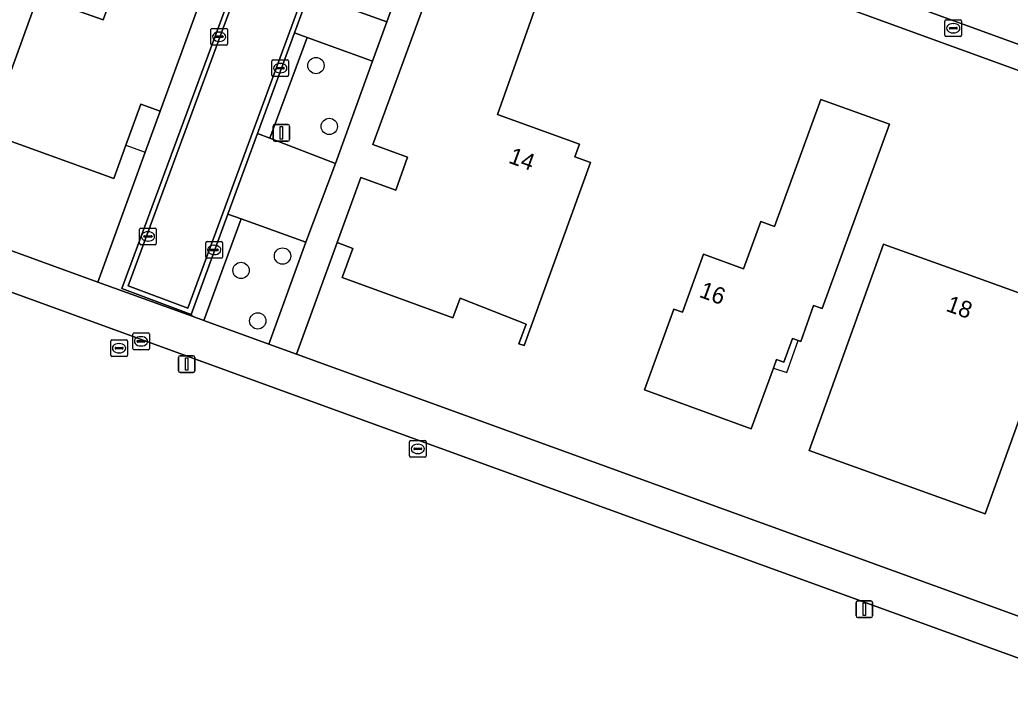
# Model space of a CAD drawing. Extents: x 155275 to 156265, y 382654 to 383635.
# Drawn here: x 155751 to 155810.4, y 382889.5 to 382930.7 of the extents above; entities that cross this region are included whole.
import ezdxf

# ---------------------------------------------------------------- set-up
doc = ezdxf.new("R2010")
doc.units = 0
for name, color, linetype in [('IMGEO_Boom', 7, 'Continuous'), ('IMGEO_Brandkraan', 7, 'Continuous'), ('IMGEO_Erf', 7, 'Continuous'), ('IMGEO_Groenvoorziening', 7, 'Continuous'), ('IMGEO_Kolk', 7, 'Continuous'), ('IMGEO_Lichtmast', 7, 'Continuous'), ('IMGEO_Loofbos', 7, 'Continuous'), ('IMGEO_Pand', 7, 'Continuous'), ('IMGEO_Pand_nummerreeks', 7, 'Continuous'), ('IMGEO_Pand_overbouw', 7, 'Continuous'), ('IMGEO_Parkeervlak_open', 7, 'Continuous'), ('IMGEO_Rijbaan_lokaal_gesloten', 7, 'Continuous'), ('IMGEO_Rijbaan_lokaal_open', 7, 'Continuous'), ('IMGEO_Rioolput', 7, 'Continuous'), ('IMGEO_Voetpad_open', 7, 'Continuous')]:
    doc.layers.add(name, color=color, linetype=linetype)

msp = doc.modelspace()

# ---------------------------------------------------------------- linework, layer by layer
at = {"layer": 'IMGEO_Boom'}
for centre in [(155768.76, 382927.949), (155769.558, 382924.296), (155766.753, 382916.521), (155764.265, 382915.657), (155765.27, 382912.636)]:
    msp.add_circle(centre, 0.489, dxfattribs=at)
at = {"layer": 'IMGEO_Brandkraan'}
for p, q in [((155806.471, 382929.76), (155806.471, 382930.612)), ((155806.546, 382930.686), (155807.398, 382930.686)), ((155806.773, 382930.229), (155807.171, 382930.229)), ((155806.959, 382930.466), (155806.984, 382930.466)), ((155807.472, 382930.612), (155807.472, 382929.76)), ((155807.398, 382929.686), (155806.546, 382929.686)), ((155806.73, 382930.18), (155806.73, 382930.192)), ((155807.168, 382930.143), (155806.77, 382930.143)), ((155806.982, 382929.906), (155806.957, 382929.906)), ((155807.214, 382930.192), (155807.214, 382930.18))]:
    msp.add_line(p, q, dxfattribs=at)
for points in [[(155806.471, 382929.76), (155806.471, 382930.612)], [(155806.546, 382930.686), (155807.398, 382930.686)], [(155807.472, 382930.612), (155807.472, 382929.76)], [(155807.398, 382929.686), (155806.546, 382929.686)]]:
    msp.add_lwpolyline(points, dxfattribs=at)
for centre, radius, start, end in [((155806.548, 382930.61), 0.0765, 91.55205, 178.44795), ((155806.548, 382930.61), 0.0765, 91.55205, 178.44795), ((155806.77, 382930.189), 0.0403, 85.87752, 175.75265), ((155807.175, 382930.191), 0.0386, 1.73085, 96.63898), ((155807.396, 382930.61), 0.0765, 1.55205, 88.44795), ((155807.396, 382930.61), 0.0765, 1.55205, 88.44795), ((155806.548, 382929.762), 0.0765, 181.55205, 268.44795), ((155806.548, 382929.762), 0.0765, 181.55205, 268.44795), ((155806.767, 382930.179), 0.0366, 178.93798, 274.71019), ((155807.171, 382930.186), 0.043, 264.86636, 352.45326), ((155807.396, 382929.762), 0.0765, 271.55205, 358.44795), ((155807.396, 382929.762), 0.0765, 271.55205, 358.44795)]:
    msp.add_arc(centre, radius, start, end, dxfattribs=at)
for centre, major_axis, ratio, start_param, end_param in [((155806.958, 382930.186), (-0.387, 0.002), 0.722429, 4.712389, 7.853982), ((155806.983, 382930.186), (-0.39, 0.002), 0.717154, 1.570796, 4.712389)]:
    msp.add_ellipse(centre, major_axis=major_axis, ratio=ratio, start_param=start_param, end_param=end_param, dxfattribs=at)
at = {"layer": 'IMGEO_Erf'}
msp.add_lwpolyline([(155687.76, 382939.71), (155755.688, 382914.965), (155758.527, 382922.75), (155759.423, 382925.217), (155758.257, 382925.64), (155757.362, 382923.173), (155756.634, 382921.166), (155749.104, 382923.897), (155752.078, 382932.095), (155756.001, 382930.696), (155756.874, 382933.113), (155758.826, 382938.522), (155755.741, 382939.635), (155758.254, 382946.596), (155763.431, 382944.727), (155762.488, 382941.996), (155765.175, 382941.027), (155765.55, 382942.058)], dxfattribs=at)
for points in [[(155858.578, 382910.318), (155778.11, 382939.582), (155776.003, 382933.692), (155781.968, 382931.558), (155779.643, 382925.014), (155784.554, 382923.227), (155784.283, 382922.477), (155785.216, 382922.133), (155781.233, 382911.153), (155780.932, 382911.263), (155781.358, 382912.438), (155777.396, 382913.993), (155776.968, 382912.818), (155770.335, 382915.238), (155770.972, 382916.985), (155770.033, 382917.328), (155767.593, 382910.639), (155854.498, 382879.089), (155856.191, 382884.092), (155849.881, 382886.353), (155855.747, 382902.481), (155860.835, 382896.859), (155862.363, 382901.052), (155857.263, 382906.66)], [(155799.119, 382913.373), (155798.593, 382913.564), (155797.827, 382911.392), (155797.667, 382911.454), (155797.338, 382911.582), (155796.815, 382910.155), (155796.373, 382910.316), (155796.184, 382909.801), (155794.846, 382906.153), (155788.459, 382908.493), (155790.224, 382913.329), (155790.743, 382913.151), (155792.004, 382916.632), (155794.386, 382915.756), (155795.428, 382918.588), (155796.245, 382918.296), (155799.029, 382925.92), (155803.141, 382924.424)], [(155808.882, 382901.058), (155798.327, 382904.865), (155802.783, 382917.235), (155803.058, 382917.132), (155807.739, 382915.451), (155813.345, 382913.432)]]:
    msp.add_lwpolyline(points, close=True, dxfattribs=at)
at = {"layer": 'IMGEO_Groenvoorziening'}
msp.add_lwpolyline([(155771.591, 382938.81), (155771.328, 382938.077), (155769.086, 382931.986), (155773.001, 382930.565), (155775.233, 382936.669)], dxfattribs=at)
for points in [[(155772.151, 382928.213), (155768.224, 382929.634), (155765.995, 382923.592), (155769.933, 382922.082)], [(155768.144, 382917.364), (155764.277, 382918.755), (155762.029, 382912.659), (155765.941, 382911.239)]]:
    msp.add_lwpolyline(points, close=True, dxfattribs=at)
at = {"layer": 'IMGEO_Kolk'}
for p, q in [((155762.453, 382929.252), (155762.453, 382930.104)), ((155762.528, 382930.178), (155763.38, 382930.178)), ((155762.712, 382929.672), (155762.712, 382929.684)), ((155763.15, 382929.635), (155762.752, 382929.635)), ((155762.755, 382929.721), (155763.153, 382929.721)), ((155762.941, 382929.958), (155762.966, 382929.958)), ((155763.196, 382929.684), (155763.196, 382929.672)), ((155763.454, 382930.104), (155763.454, 382929.252)), ((155763.38, 382929.178), (155762.528, 382929.178)), ((155762.964, 382929.398), (155762.939, 382929.398)), ((155766.117, 382927.368), (155766.117, 382928.22)), ((155766.192, 382928.294), (155767.044, 382928.294)), ((155766.605, 382928.074), (155766.63, 382928.074)), ((155767.118, 382928.22), (155767.118, 382927.368)), ((155767.044, 382927.294), (155766.192, 382927.294)), ((155766.376, 382927.788), (155766.376, 382927.8)), ((155766.814, 382927.751), (155766.416, 382927.751)), ((155766.419, 382927.837), (155766.817, 382927.837)), ((155766.628, 382927.514), (155766.603, 382927.514)), ((155766.86, 382927.8), (155766.86, 382927.788)), ((155758.185, 382917.275), (155758.185, 382918.127)), ((155758.26, 382918.201), (155759.112, 382918.201)), ((155758.673, 382917.981), (155758.698, 382917.981)), ((155759.186, 382918.127), (155759.186, 382917.275)), ((155759.112, 382917.201), (155758.26, 382917.201)), ((155758.444, 382917.695), (155758.444, 382917.707)), ((155758.882, 382917.658), (155758.484, 382917.658)), ((155758.487, 382917.744), (155758.885, 382917.744)), ((155758.696, 382917.421), (155758.671, 382917.421)), ((155758.928, 382917.707), (155758.928, 382917.695)), ((155762.156, 382916.462), (155762.156, 382917.314)), ((155762.231, 382917.388), (155763.083, 382917.388)), ((155762.644, 382917.168), (155762.669, 382917.168)), ((155763.157, 382917.314), (155763.157, 382916.462)), ((155762.415, 382916.882), (155762.415, 382916.894)), ((155762.853, 382916.845), (155762.455, 382916.845)), ((155762.458, 382916.931), (155762.856, 382916.931)), ((155762.667, 382916.608), (155762.642, 382916.608)), ((155762.899, 382916.894), (155762.899, 382916.882)), ((155763.083, 382916.388), (155762.231, 382916.388))]:
    msp.add_line(p, q, dxfattribs=at)
for points in [[(155762.453, 382929.252), (155762.453, 382930.104)], [(155762.528, 382930.178), (155763.38, 382930.178)], [(155763.454, 382930.104), (155763.454, 382929.252)], [(155763.38, 382929.178), (155762.528, 382929.178)], [(155766.117, 382927.368), (155766.117, 382928.22)], [(155766.192, 382928.294), (155767.044, 382928.294)], [(155767.118, 382928.22), (155767.118, 382927.368)], [(155767.044, 382927.294), (155766.192, 382927.294)], [(155758.185, 382917.275), (155758.185, 382918.127)], [(155758.26, 382918.201), (155759.112, 382918.201)], [(155759.186, 382918.127), (155759.186, 382917.275)], [(155759.112, 382917.201), (155758.26, 382917.201)], [(155762.156, 382916.462), (155762.156, 382917.314)], [(155762.231, 382917.388), (155763.083, 382917.388)], [(155763.157, 382917.314), (155763.157, 382916.462)], [(155763.083, 382916.388), (155762.231, 382916.388)]]:
    msp.add_lwpolyline(points, dxfattribs=at)
for centre, radius, start, end in [((155762.53, 382930.102), 0.0765, 91.55205, 178.44795), ((155762.53, 382930.102), 0.0765, 91.55205, 178.44795), ((155762.752, 382929.681), 0.0403, 85.87752, 175.75265), ((155762.749, 382929.671), 0.0366, 178.93798, 274.71019), ((155763.153, 382929.678), 0.043, 264.86636, 352.45326), ((155763.157, 382929.683), 0.0386, 1.73085, 96.63898), ((155763.378, 382930.102), 0.0765, 1.55205, 88.44795), ((155763.378, 382930.102), 0.0765, 1.55205, 88.44795), ((155762.53, 382929.254), 0.0765, 181.55205, 268.44795), ((155762.53, 382929.254), 0.0765, 181.55205, 268.44795), ((155763.378, 382929.254), 0.0765, 271.55205, 358.44795), ((155763.378, 382929.254), 0.0765, 271.55205, 358.44795), ((155766.194, 382928.218), 0.0765, 91.55205, 178.44795), ((155766.194, 382928.218), 0.0765, 91.55205, 178.44795), ((155767.042, 382928.218), 0.0765, 1.55205, 88.44795), ((155767.042, 382928.218), 0.0765, 1.55205, 88.44795), ((155766.194, 382927.37), 0.0765, 181.55205, 268.44795), ((155766.194, 382927.37), 0.0765, 181.55205, 268.44795), ((155766.416, 382927.797), 0.0403, 85.87752, 175.75265), ((155766.413, 382927.787), 0.0366, 178.93798, 274.71019), ((155766.817, 382927.794), 0.043, 264.86636, 352.45326), ((155766.821, 382927.799), 0.0386, 1.73085, 96.63898), ((155767.042, 382927.37), 0.0765, 271.55205, 358.44795), ((155767.042, 382927.37), 0.0765, 271.55205, 358.44795), ((155758.262, 382918.125), 0.0765, 91.55205, 178.44795), ((155758.262, 382918.125), 0.0765, 91.55205, 178.44795), ((155759.11, 382918.125), 0.0765, 1.55205, 88.44795), ((155759.11, 382918.125), 0.0765, 1.55205, 88.44795), ((155758.262, 382917.277), 0.0765, 181.55205, 268.44795), ((155758.262, 382917.277), 0.0765, 181.55205, 268.44795), ((155758.484, 382917.704), 0.0403, 85.87752, 175.75265), ((155758.481, 382917.694), 0.0366, 178.93798, 274.71019), ((155758.885, 382917.701), 0.043, 264.86636, 352.45326), ((155758.889, 382917.706), 0.0386, 1.73085, 96.63898), ((155759.11, 382917.277), 0.0765, 271.55205, 358.44795), ((155759.11, 382917.277), 0.0765, 271.55205, 358.44795), ((155762.233, 382917.312), 0.0765, 91.55205, 178.44795), ((155762.233, 382917.312), 0.0765, 91.55205, 178.44795), ((155763.081, 382917.312), 0.0765, 1.55205, 88.44795), ((155763.081, 382917.312), 0.0765, 1.55205, 88.44795), ((155762.455, 382916.891), 0.0403, 85.87752, 175.75265), ((155762.452, 382916.881), 0.0366, 178.93798, 274.71019), ((155762.856, 382916.888), 0.043, 264.86636, 352.45326), ((155762.86, 382916.893), 0.0386, 1.73085, 96.63898), ((155762.233, 382916.464), 0.0765, 181.55205, 268.44795), ((155762.233, 382916.464), 0.0765, 181.55205, 268.44795), ((155763.081, 382916.464), 0.0765, 271.55205, 358.44795), ((155763.081, 382916.464), 0.0765, 271.55205, 358.44795)]:
    msp.add_arc(centre, radius, start, end, dxfattribs=at)
for centre, major_axis, ratio, start_param, end_param in [((155762.94, 382929.678), (-0.387, 0.002), 0.722429, 4.712389, 7.853982), ((155762.965, 382929.678), (-0.39, 0.002), 0.717154, 1.570796, 4.712389), ((155766.604, 382927.794), (-0.387, 0.002), 0.722429, 4.712389, 7.853982), ((155766.629, 382927.794), (-0.39, 0.002), 0.717154, 1.570796, 4.712389), ((155758.672, 382917.701), (-0.387, 0.002), 0.722429, 4.712389, 7.853982), ((155758.697, 382917.701), (-0.39, 0.002), 0.717154, 1.570796, 4.712389), ((155762.643, 382916.888), (-0.387, 0.002), 0.722429, 4.712389, 7.853982), ((155762.668, 382916.888), (-0.39, 0.002), 0.717154, 1.570796, 4.712389)]:
    msp.add_ellipse(centre, major_axis=major_axis, ratio=ratio, start_param=start_param, end_param=end_param, dxfattribs=at)
at = {"layer": 'IMGEO_Lichtmast'}
for p, q in [((155766.187, 382923.512), (155766.187, 382924.312)), ((155766.187, 382924.312), (155766.187, 382923.512)), ((155766.287, 382924.412), (155767.077, 382924.412)), ((155767.077, 382924.412), (155766.287, 382924.412)), ((155767.177, 382924.312), (155767.177, 382923.512)), ((155767.177, 382923.512), (155767.177, 382924.312)), ((155767.077, 382923.412), (155766.287, 382923.412)), ((155766.287, 382923.412), (155767.077, 382923.412)), ((155760.513, 382909.644), (155760.513, 382910.444)), ((155760.513, 382910.444), (155760.513, 382909.644)), ((155760.613, 382910.544), (155761.403, 382910.544)), ((155761.403, 382910.544), (155760.613, 382910.544)), ((155761.503, 382910.444), (155761.503, 382909.644)), ((155761.503, 382909.644), (155761.503, 382910.444)), ((155761.403, 382909.544), (155760.613, 382909.544)), ((155760.613, 382909.544), (155761.403, 382909.544)), ((155801.242, 382895.842), (155802.032, 382895.842)), ((155802.032, 382895.842), (155801.242, 382895.842)), ((155801.142, 382894.942), (155801.142, 382895.742)), ((155801.142, 382895.742), (155801.142, 382894.942)), ((155802.132, 382895.742), (155802.132, 382894.942)), ((155802.132, 382894.942), (155802.132, 382895.742)), ((155802.032, 382894.842), (155801.242, 382894.842)), ((155801.242, 382894.842), (155802.032, 382894.842))]:
    msp.add_line(p, q, dxfattribs=at)
for points in [[(155766.607, 382924.287), (155766.757, 382924.287), (155766.757, 382923.537), (155766.607, 382923.537), (155766.607, 382924.287)], [(155760.933, 382910.419), (155761.083, 382910.419), (155761.083, 382909.669), (155760.933, 382909.669), (155760.933, 382910.419)], [(155801.562, 382895.717), (155801.712, 382895.717), (155801.712, 382894.967), (155801.562, 382894.967), (155801.562, 382895.717)]]:
    msp.add_lwpolyline(points, dxfattribs=at)
for centre, start, end in [((155766.287, 382924.312), 90, 180), ((155766.287, 382924.312), 90, 180), ((155767.077, 382924.312), 0, 90), ((155767.077, 382924.312), 360, 90), ((155766.287, 382923.512), 180, 270), ((155766.287, 382923.512), 180, 270), ((155767.077, 382923.512), 270, 0), ((155767.077, 382923.512), 270, 0), ((155760.613, 382910.444), 90, 180), ((155760.613, 382910.444), 90, 180), ((155761.403, 382910.444), 0, 90), ((155761.403, 382910.444), 360, 90), ((155760.613, 382909.644), 180, 270), ((155760.613, 382909.644), 180, 270), ((155761.403, 382909.644), 270, 0), ((155761.403, 382909.644), 270, 0), ((155801.242, 382895.742), 90, 180), ((155801.242, 382895.742), 90, 180), ((155802.032, 382895.742), 0, 90), ((155802.032, 382895.742), 360, 90), ((155801.242, 382894.942), 180, 270), ((155801.242, 382894.942), 180, 270), ((155802.032, 382894.942), 270, 0), ((155802.032, 382894.942), 270, 0)]:
    msp.add_arc(centre, 0.1, start, end, dxfattribs=at)
at = {"layer": 'IMGEO_Loofbos'}
msp.add_lwpolyline([(155962.277, 382837.428), (155865.28, 382872.649), (155863.949, 382873.132), (155772.846, 382906.212), (155660.759, 382947.032), (155649.875, 382951.072)], dxfattribs=at)
at = {"layer": 'IMGEO_Pand'}
for points in [[(155765.175, 382941.027), (155762.488, 382941.996), (155763.431, 382944.727), (155758.254, 382946.596), (155755.741, 382939.635), (155758.826, 382938.522), (155756.874, 382933.113), (155756.001, 382930.696), (155752.078, 382932.095), (155749.104, 382923.897), (155756.634, 382921.166), (155757.362, 382923.173), (155758.257, 382925.64), (155759.423, 382925.217)], [(155784.554, 382923.227), (155779.643, 382925.014), (155781.968, 382931.558), (155776.003, 382933.692), (155772.176, 382923.203), (155774.245, 382922.448), (155773.539, 382920.477), (155771.459, 382921.236), (155770.033, 382917.328), (155770.972, 382916.985), (155770.335, 382915.238), (155776.968, 382912.818), (155777.396, 382913.993), (155781.358, 382912.438), (155780.932, 382911.263), (155781.233, 382911.153), (155785.216, 382922.133), (155784.283, 382922.477)], [(155803.141, 382924.424), (155799.029, 382925.92), (155796.245, 382918.296), (155795.428, 382918.588), (155794.386, 382915.756), (155792.004, 382916.632), (155790.743, 382913.151), (155790.224, 382913.329), (155788.459, 382908.493), (155794.846, 382906.153), (155796.184, 382909.801), (155796.373, 382910.316), (155796.815, 382910.155), (155797.338, 382911.582), (155797.667, 382911.454), (155797.827, 382911.392), (155798.593, 382913.564), (155799.119, 382913.373)], [(155813.345, 382913.432), (155807.739, 382915.451), (155803.058, 382917.132), (155802.783, 382917.235), (155798.327, 382904.865), (155808.882, 382901.058)]]:
    msp.add_lwpolyline(points, close=True, dxfattribs=at)
at = {"layer": 'IMGEO_Pand_overbouw'}
for points in [[(155757.362, 382923.173), (155758.527, 382922.75), (155759.423, 382925.217), (155758.257, 382925.64)], [(155796.184, 382909.801), (155796.983, 382909.529), (155797.667, 382911.454), (155797.338, 382911.582), (155796.815, 382910.155), (155796.373, 382910.316)]]:
    msp.add_lwpolyline(points, close=True, dxfattribs=at)
at = {"layer": 'IMGEO_Parkeervlak_open'}
for points in [[(155773.001, 382930.565), (155769.086, 382931.986), (155768.332, 382932.259), (155767.47, 382929.907), (155768.224, 382929.634), (155772.151, 382928.213)], [(155769.933, 382922.082), (155765.995, 382923.592), (155765.257, 382923.875), (155763.483, 382919.04), (155764.277, 382918.755), (155768.144, 382917.364)]]:
    msp.add_lwpolyline(points, close=True, dxfattribs=at)
at = {"layer": 'IMGEO_Rijbaan_lokaal_gesloten'}
msp.add_lwpolyline([(155768.503, 382944.698), (155768.234, 382944.798), (155766.869, 382941.017), (155766.677, 382940.485), (155766.362, 382939.613), (155766.325, 382939.51), (155757.114, 382914.571), (155761.275, 382913.02), (155763.483, 382919.04), (155765.257, 382923.875), (155767.47, 382929.907), (155768.332, 382932.259), (155770.477, 382938.105), (155770.567, 382938.351), (155770.802, 382938.991), (155771.045, 382939.658), (155772.36, 382943.272), (155772.086, 382943.374), (155770.526, 382939.085), (155761.085, 382913.388), (155757.497, 382914.737), (155766.597, 382939.416)], close=True, dxfattribs=at)
at = {"layer": 'IMGEO_Rijbaan_lokaal_open'}
for points in [[(155779.611, 382944.594), (155777.389, 382945.399), (155777.321, 382945.404), (155773.631, 382946.766), (155772.36, 382943.272), (155776.11, 382941.886), (155776.209, 382941.85), (155778.386, 382941.058), (155778.616, 382940.974), (155865.403, 382909.39), (155867.798, 382908.519), (155871.528, 382907.192), (155872.823, 382910.756), (155869.136, 382912.156), (155866.718, 382913.032)], [(155772.086, 382943.374), (155768.503, 382944.698), (155766.597, 382939.416), (155757.497, 382914.737), (155761.085, 382913.388), (155770.526, 382939.085)]]:
    msp.add_lwpolyline(points, close=True, dxfattribs=at)
at = {"layer": 'IMGEO_Rioolput'}
for p, q in [((155757.769, 382910.982), (155757.769, 382911.834)), ((155757.844, 382911.908), (155758.696, 382911.908)), ((155758.77, 382911.834), (155758.77, 382910.982)), ((155756.452, 382910.569), (155756.452, 382911.421)), ((155756.527, 382911.495), (155757.379, 382911.495)), ((155756.94, 382911.275), (155756.965, 382911.275)), ((155757.453, 382911.421), (155757.453, 382910.569)), ((155758.028, 382911.402), (155758.028, 382911.414)), ((155758.466, 382911.365), (155758.068, 382911.365)), ((155758.071, 382911.451), (155758.469, 382911.451)), ((155758.257, 382911.688), (155758.282, 382911.688)), ((155758.512, 382911.414), (155758.512, 382911.402)), ((155756.711, 382910.989), (155756.711, 382911.001)), ((155757.149, 382910.952), (155756.751, 382910.952)), ((155756.754, 382911.038), (155757.152, 382911.038)), ((155756.963, 382910.715), (155756.938, 382910.715)), ((155757.195, 382911.001), (155757.195, 382910.989)), ((155758.696, 382910.908), (155757.844, 382910.908)), ((155758.28, 382911.128), (155758.255, 382911.128)), ((155757.379, 382910.495), (155756.527, 382910.495)), ((155774.365, 382904.532), (155774.365, 382905.384)), ((155774.44, 382905.458), (155775.292, 382905.458)), ((155775.366, 382905.384), (155775.366, 382904.532)), ((155774.624, 382904.952), (155774.624, 382904.964)), ((155775.062, 382904.915), (155774.664, 382904.915)), ((155774.667, 382905.001), (155775.065, 382905.001)), ((155774.853, 382905.238), (155774.878, 382905.238)), ((155775.108, 382904.964), (155775.108, 382904.952)), ((155775.292, 382904.458), (155774.44, 382904.458)), ((155774.876, 382904.678), (155774.851, 382904.678))]:
    msp.add_line(p, q, dxfattribs=at)
for points in [[(155757.769, 382910.982), (155757.769, 382911.834)], [(155757.844, 382911.908), (155758.696, 382911.908)], [(155758.77, 382911.834), (155758.77, 382910.982)], [(155756.452, 382910.569), (155756.452, 382911.421)], [(155756.527, 382911.495), (155757.379, 382911.495)], [(155757.453, 382911.421), (155757.453, 382910.569)], [(155758.696, 382910.908), (155757.844, 382910.908)], [(155757.379, 382910.495), (155756.527, 382910.495)], [(155774.365, 382904.532), (155774.365, 382905.384)], [(155774.44, 382905.458), (155775.292, 382905.458)], [(155775.366, 382905.384), (155775.366, 382904.532)], [(155775.292, 382904.458), (155774.44, 382904.458)]]:
    msp.add_lwpolyline(points, dxfattribs=at)
for centre, radius, start, end in [((155757.846, 382911.832), 0.0765, 91.55205, 178.44795), ((155757.846, 382911.832), 0.0765, 91.55205, 178.44795), ((155758.694, 382911.832), 0.0765, 1.55205, 88.44795), ((155758.694, 382911.832), 0.0765, 1.55205, 88.44795), ((155756.529, 382911.419), 0.0765, 91.55205, 178.44795), ((155756.529, 382911.419), 0.0765, 91.55205, 178.44795), ((155757.377, 382911.419), 0.0765, 1.55205, 88.44795), ((155757.377, 382911.419), 0.0765, 1.55205, 88.44795), ((155758.068, 382911.411), 0.0403, 85.87752, 175.75265), ((155758.065, 382911.401), 0.0366, 178.93798, 274.71019), ((155758.469, 382911.408), 0.043, 264.86636, 352.45326), ((155758.473, 382911.413), 0.0386, 1.73085, 96.63898), ((155756.751, 382910.998), 0.0403, 85.87752, 175.75265), ((155756.748, 382910.988), 0.0366, 178.93798, 274.71019), ((155757.152, 382910.995), 0.043, 264.86636, 352.45326), ((155757.156, 382911), 0.0386, 1.73085, 96.63898), ((155757.846, 382910.984), 0.0765, 181.55205, 268.44795), ((155757.846, 382910.984), 0.0765, 181.55205, 268.44795), ((155758.694, 382910.984), 0.0765, 271.55205, 358.44795), ((155758.694, 382910.984), 0.0765, 271.55205, 358.44795), ((155756.529, 382910.571), 0.0765, 181.55205, 268.44795), ((155756.529, 382910.571), 0.0765, 181.55205, 268.44795), ((155757.377, 382910.571), 0.0765, 271.55205, 358.44795), ((155757.377, 382910.571), 0.0765, 271.55205, 358.44795), ((155774.442, 382905.382), 0.0765, 91.55205, 178.44795), ((155774.442, 382905.382), 0.0765, 91.55205, 178.44795), ((155775.29, 382905.382), 0.0765, 1.55205, 88.44795), ((155775.29, 382905.382), 0.0765, 1.55205, 88.44795), ((155774.664, 382904.961), 0.0403, 85.87752, 175.75265), ((155774.661, 382904.951), 0.0366, 178.93798, 274.71019), ((155775.065, 382904.958), 0.043, 264.86636, 352.45326), ((155775.069, 382904.963), 0.0386, 1.73085, 96.63898), ((155774.442, 382904.534), 0.0765, 181.55205, 268.44795), ((155774.442, 382904.534), 0.0765, 181.55205, 268.44795), ((155775.29, 382904.534), 0.0765, 271.55205, 358.44795), ((155775.29, 382904.534), 0.0765, 271.55205, 358.44795)]:
    msp.add_arc(centre, radius, start, end, dxfattribs=at)
for centre, major_axis, ratio, start_param, end_param in [((155756.939, 382910.995), (-0.387, 0.002), 0.722429, 4.712389, 7.853982), ((155756.964, 382910.995), (-0.39, 0.002), 0.717154, 1.570796, 4.712389), ((155758.256, 382911.408), (-0.387, 0.002), 0.722429, 4.712389, 7.853982), ((155758.281, 382911.408), (-0.39, 0.002), 0.717154, 1.570796, 4.712389), ((155774.852, 382904.958), (-0.387, 0.002), 0.722429, 4.712389, 7.853982), ((155774.877, 382904.958), (-0.39, 0.002), 0.717154, 1.570796, 4.712389)]:
    msp.add_ellipse(centre, major_axis=major_axis, ratio=ratio, start_param=start_param, end_param=end_param, dxfattribs=at)
at = {"layer": 'IMGEO_Voetpad_open'}
for points in [[(155687.76, 382939.71), (155661.6, 382949.239), (155660.759, 382947.032), (155772.846, 382906.212), (155863.949, 382873.132), (155864.759, 382875.363), (155860.495, 382876.912), (155859.753, 382877.182), (155855.852, 382878.598), (155854.498, 382879.089), (155767.593, 382910.639), (155765.941, 382911.239), (155762.029, 382912.659), (155761.338, 382912.91), (155757.172, 382914.424), (155755.688, 382914.965)], [(155766.362, 382939.613), (155766.677, 382940.485), (155765.175, 382941.027), (155759.423, 382925.217), (155758.527, 382922.75), (155755.688, 382914.965), (155757.172, 382914.424), (155761.338, 382912.91), (155761.275, 382913.02), (155757.114, 382914.571), (155766.325, 382939.51)], [(155778.616, 382940.974), (155778.11, 382939.582), (155858.578, 382910.318), (155864.887, 382908.023), (155865.403, 382909.39)], [(155768.224, 382929.634), (155767.47, 382929.907), (155765.257, 382923.875), (155765.995, 382923.592)], [(155764.277, 382918.755), (155763.483, 382919.04), (155761.275, 382913.02), (155761.338, 382912.91), (155762.029, 382912.659)]]:
    msp.add_lwpolyline(points, close=True, dxfattribs=at)
msp.add_lwpolyline([(155775.492, 382940.561), (155776.556, 382940.189), (155775.233, 382936.669), (155773.001, 382930.565), (155772.151, 382928.213), (155769.933, 382922.082), (155768.144, 382917.364), (155765.941, 382911.239), (155767.593, 382910.639), (155770.033, 382917.328), (155771.459, 382921.236), (155773.539, 382920.477), (155774.245, 382922.448), (155772.176, 382923.203), (155776.003, 382933.692)], dxfattribs=at)

# ---------------------------------------------------------------- texts
at = {"layer": 'IMGEO_Pand_nummerreeks'}
for s, rotation, p in [('14', 340.00472, (155780.248, 382922.133)), ('16', 339.80859, (155791.679, 382914.088)), ('18', 340.19352, (155806.481, 382913.247))]:
    msp.add_text(s, height=1, rotation=rotation, dxfattribs=at).set_placement(p)

doc.saveas('drawing.dxf')
